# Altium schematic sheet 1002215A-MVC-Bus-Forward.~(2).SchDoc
size B; Organization: Monterey Bay Aquarium Research Institute; Address1: 7700 Sandholdt Rd; Address2: Moss Landing, CA 95039-9644; CompanyName: MBARI; PageSetup: Record=PageOptions|CenterHorizontal=True|CenterVertical=True|PrintScale=1.09|XCorrection=1.00|YCorrection=1.00|PrintKind=0|BorderSize=5000000|LeftOffset=0|BottomOffset=0|Orientation=2|PaperLength=4318|PaperWidth=2794|Scale=100|PaperSource=15|PrintQuality=600|MediaType=1|DitherType=0|PaperKind=11x17|PrintScaleMode=1
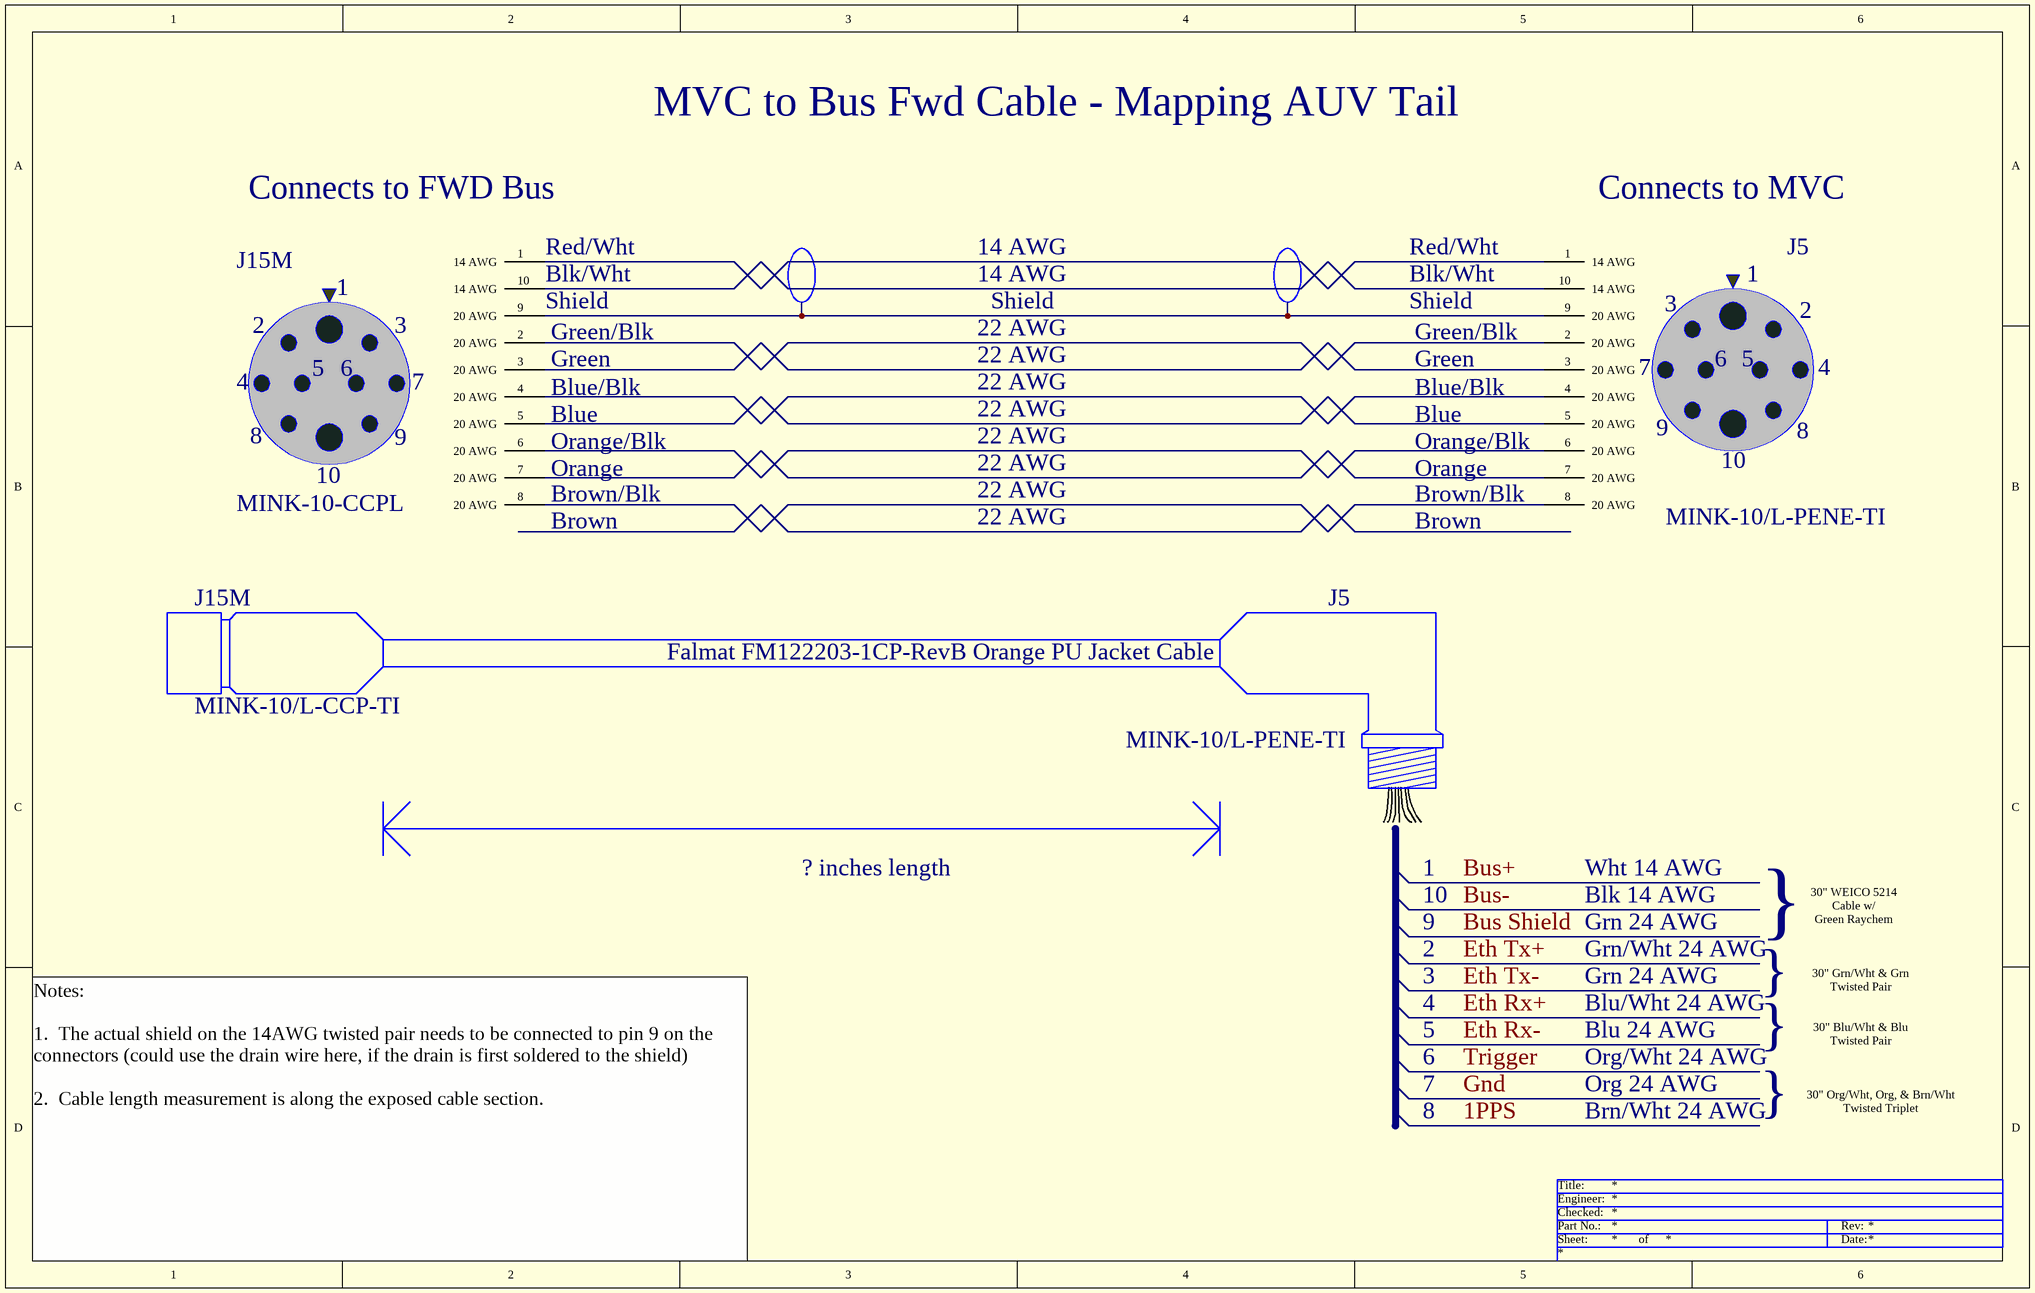
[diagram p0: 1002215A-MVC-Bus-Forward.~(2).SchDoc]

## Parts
(Parts that share a designator on the sheet are numbered #1, #2 ... from top to bottom, then left to right.)
J5#1  MINK-10/L-PENE-TI
J5#2  MINK-10/L-PENE-TI
J15M#1  MINK-10-CCPL
J15M#2  MINK-10/L-CCP-TI

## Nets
NetJ5#1_1: J5#1.1(14_AWG) J15M#1.1(14_AWG)
NetJ5#1_2: J5#1.2(20_AWG) J15M#1.2(20_AWG)
NetJ5#1_3: J5#1.3(20_AWG) J15M#1.3(20_AWG)
NetJ5#1_4: J5#1.4(20_AWG) J15M#1.4(20_AWG)
NetJ5#1_5: J5#1.5(20_AWG) J15M#1.5(20_AWG)
NetJ5#1_6: J5#1.6(20_AWG) J15M#1.6(20_AWG)
NetJ5#1_7: J5#1.7(20_AWG) J15M#1.7(20_AWG)
NetJ5#1_8: J5#1.8(20_AWG) J15M#1.8(20_AWG)
NetJ5#1_9: J5#1.9(20_AWG) J15M#1.9(20_AWG)
NetJ5#1_10: J5#1.10(14_AWG) J15M#1.10(14_AWG)

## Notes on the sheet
- MVC to Bus Fwd Cable - Mapping AUV Tail
- Connects to FWD Bus
- Connects to MVC
- (near J15M#1) Red/Wht
- (near J15M#1) Blk/Wht
- 14 AWG
- Red/Wht
- Blk/Wht
- (near J15M#1) Shield
- (near J15M#1) Green
- (near J15M#1) Green/Blk
- 22 AWG
- Shield
- Green
- Green/Blk
- (near J15M#1) Blue/Blk
- (near J15M#1) Blue
- Blue/Blk
- Blue
- (near J15M#1) Brown/Blk
- (near J15M#1) Orange
- (near J15M#1) Orange/Blk
- Brown/Blk
- Orange
- (near J5#1) Orange/Blk
- (near J15M#1) Brown
- Brown
- Falmat FM122203-1CP-RevB Orange PU Jacket Cable
- ? inches length
- 1
- 10
- Wht 14 AWG
- Blk 14 AWG
- 2
- 9
- Grn 24 AWG
- Grn/Wht 24 AWG
- }
- 30" WEICO 5214 Cable w/
  Green Raychem Drain
- 3
- 4
- 5
- Blu/Wht 24 AWG
- Blu 24 AWG
- 30" Grn/Wht & Grn
  Twisted Pair
- 30" Blu/Wht & Blu
  Twisted Pair
- 6
- 7
- Org/Wht 24 AWG
- Org 24 AWG
- 30" Org/Wht, Org, & Brn/Wht
  Twisted Triplet
- 8
- Brn/Wht 24 AWG
- Notes:
  1.  The actual shield on the 14AWG twisted pair needs to be connected to pin 9 on the connectors (could use the drain wire here, if the drain is first soldered to the shield)
  2.  Cable length measurement is along the exposed cable section.

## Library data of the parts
J5#1 = SEACON-MINK-10-BCR-PINS: Manufacturer: Seacon
J5#2 = CONN-MIN-PENE-LARGE: Seacon MIN Penetrator
J15M#1 = SEACON-MINK-10-CCP-SOC: Seacon MINK-10/L-CCP Connector; DescSheet: Cable; View: Female Face
J15M#2 = CONN-MIN-CCP-LARGE: Seacon MIN Connector CCP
